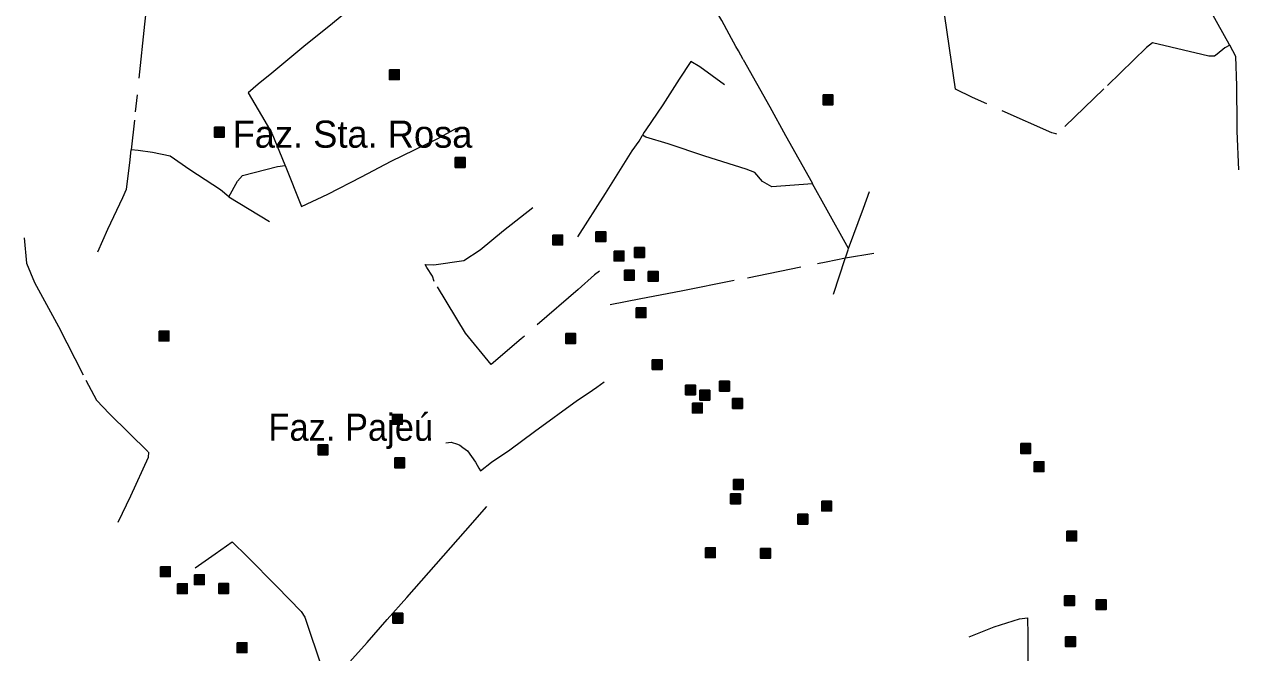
# Model space of a CAD drawing. Extents: x 393.5 to 446.9, y 8064.8 to 8120.4.
# Drawn here: x 410.47 to 417.64, y 8111.65 to 8115.35 of the extents above; entities that cross this region are included whole.
import ezdxf

# ---------------------------------------------------------------- set-up
doc = ezdxf.new("R2010")
doc.units = 0
doc.header["$LTSCALE"] = 0.064
doc.linetypes.add('DOT_DASHED', pattern=[7.7, 5, -1.2, 0.3, -1.2])
doc.layers.add('2', color=7, linetype='Continuous', lineweight=25)
doc.layers.add('22', color=7, linetype='DOT_DASHED', lineweight=13)
doc.layers.add('61', color=7, linetype='Continuous')

msp = doc.modelspace()

# ---------------------------------------------------------------- hatches: boundary and pattern name
at = {"layer": '2'}
for points in [[(412.626, 8115.0857), (412.684, 8115.0857), (412.684, 8115.0277), (412.626, 8115.0277)], [(415.185, 8114.9373), (415.243, 8114.9373), (415.243, 8114.8793), (415.185, 8114.8793)], [(411.5929, 8114.7465), (411.6509, 8114.7465), (411.6509, 8114.6885), (411.5929, 8114.6885)], [(413.0148, 8114.5678), (413.0728, 8114.5678), (413.0728, 8114.5098), (413.0148, 8114.5098)], [(413.5902, 8114.1105), (413.6482, 8114.1105), (413.6482, 8114.0525), (413.5902, 8114.0525)], [(413.8448, 8114.1301), (413.9028, 8114.1301), (413.9028, 8114.0721), (413.8448, 8114.0721)], [(413.9519, 8114.016), (414.0099, 8114.016), (414.0099, 8113.958), (413.9519, 8113.958)], [(414.0725, 8114.036), (414.1305, 8114.036), (414.1305, 8113.978), (414.0725, 8113.978)], [(414.0122, 8113.9022), (414.0702, 8113.9022), (414.0702, 8113.8442), (414.0122, 8113.8442)], [(414.1529, 8113.8953), (414.2109, 8113.8953), (414.2109, 8113.8373), (414.1529, 8113.8373)], [(414.0812, 8113.6809), (414.1392, 8113.6809), (414.1392, 8113.6229), (414.0812, 8113.6229)], [(411.2667, 8113.5433), (411.3247, 8113.5433), (411.3247, 8113.4853), (411.2667, 8113.4853)], [(413.6664, 8113.5291), (413.7244, 8113.5291), (413.7244, 8113.4711), (413.6664, 8113.4711)], [(414.177, 8113.3748), (414.235, 8113.3748), (414.235, 8113.3168), (414.177, 8113.3168)], [(414.3733, 8113.2253), (414.4313, 8113.2253), (414.4313, 8113.1673), (414.3733, 8113.1673)], [(414.5742, 8113.2475), (414.6322, 8113.2475), (414.6322, 8113.1895), (414.5742, 8113.1895)], [(414.4582, 8113.1939), (414.5162, 8113.1939), (414.5162, 8113.1359), (414.4582, 8113.1359)], [(414.6506, 8113.1449), (414.7086, 8113.1449), (414.7086, 8113.0869), (414.6506, 8113.0869)], [(414.414, 8113.1183), (414.472, 8113.1183), (414.472, 8113.0603), (414.414, 8113.0603)], [(412.6438, 8113.0521), (412.7018, 8113.0521), (412.7018, 8112.9941), (412.6438, 8112.9941)], [(412.2047, 8112.8714), (412.2627, 8112.8714), (412.2627, 8112.8134), (412.2047, 8112.8134)], [(416.3509, 8112.8795), (416.4089, 8112.8795), (416.4089, 8112.8215), (416.3509, 8112.8215)], [(412.6574, 8112.7951), (412.7154, 8112.7951), (412.7154, 8112.7371), (412.6574, 8112.7371)], [(416.43, 8112.7725), (416.488, 8112.7725), (416.488, 8112.7145), (416.43, 8112.7145)], [(414.6554, 8112.6666), (414.7134, 8112.6666), (414.7134, 8112.6086), (414.6554, 8112.6086)], [(414.6391, 8112.5823), (414.6971, 8112.5823), (414.6971, 8112.5243), (414.6391, 8112.5243)], [(415.1773, 8112.5397), (415.2353, 8112.5397), (415.2353, 8112.4817), (415.1773, 8112.4817)], [(415.0364, 8112.4625), (415.0944, 8112.4625), (415.0944, 8112.4045), (415.0364, 8112.4045)], [(416.6232, 8112.3635), (416.6812, 8112.3635), (416.6812, 8112.3055), (416.6232, 8112.3055)], [(414.4907, 8112.2645), (414.5487, 8112.2645), (414.5487, 8112.2065), (414.4907, 8112.2065)], [(414.8157, 8112.2609), (414.8737, 8112.2609), (414.8737, 8112.2029), (414.8157, 8112.2029)], [(411.2747, 8112.1528), (411.3327, 8112.1528), (411.3327, 8112.0948), (411.2747, 8112.0948)], [(411.4754, 8112.1058), (411.5334, 8112.1058), (411.5334, 8112.0478), (411.4754, 8112.0478)], [(411.3752, 8112.0521), (411.4332, 8112.0521), (411.4332, 8111.9941), (411.3752, 8111.9941)], [(411.6189, 8112.053), (411.6769, 8112.053), (411.6769, 8111.995), (411.6189, 8111.995)], [(416.6096, 8111.9813), (416.6676, 8111.9813), (416.6676, 8111.9233), (416.6096, 8111.9233)], [(416.797, 8111.9577), (416.855, 8111.9577), (416.855, 8111.8997), (416.797, 8111.8997)], [(412.647, 8111.878), (412.705, 8111.878), (412.705, 8111.82), (412.647, 8111.82)], [(416.6161, 8111.7398), (416.6741, 8111.7398), (416.6741, 8111.6818), (416.6161, 8111.6818)], [(411.7272, 8111.7039), (411.7852, 8111.7039), (411.7852, 8111.6459), (411.7272, 8111.6459)]]:
    msp.add_hatch(color=256, dxfattribs=at).paths.add_polyline_path(points)

# ---------------------------------------------------------------- linework, layer by layer
for points in [[(412.626, 8115.0857), (412.684, 8115.0857), (412.684, 8115.0277), (412.626, 8115.0277)], [(415.185, 8114.9373), (415.243, 8114.9373), (415.243, 8114.8793), (415.185, 8114.8793)], [(411.5929, 8114.7465), (411.6509, 8114.7465), (411.6509, 8114.6885), (411.5929, 8114.6885)], [(413.0148, 8114.5678), (413.0728, 8114.5678), (413.0728, 8114.5098), (413.0148, 8114.5098)], [(413.5902, 8114.1105), (413.6482, 8114.1105), (413.6482, 8114.0525), (413.5902, 8114.0525)], [(413.8448, 8114.1301), (413.9028, 8114.1301), (413.9028, 8114.0721), (413.8448, 8114.0721)], [(413.9519, 8114.016), (414.0099, 8114.016), (414.0099, 8113.958), (413.9519, 8113.958)], [(414.0725, 8114.036), (414.1305, 8114.036), (414.1305, 8113.978), (414.0725, 8113.978)], [(414.0122, 8113.9022), (414.0702, 8113.9022), (414.0702, 8113.8442), (414.0122, 8113.8442)], [(414.1529, 8113.8953), (414.2109, 8113.8953), (414.2109, 8113.8373), (414.1529, 8113.8373)], [(414.0812, 8113.6809), (414.1392, 8113.6809), (414.1392, 8113.6229), (414.0812, 8113.6229)], [(411.2667, 8113.5433), (411.3247, 8113.5433), (411.3247, 8113.4853), (411.2667, 8113.4853)], [(413.6664, 8113.5291), (413.7244, 8113.5291), (413.7244, 8113.4711), (413.6664, 8113.4711)], [(414.177, 8113.3748), (414.235, 8113.3748), (414.235, 8113.3168), (414.177, 8113.3168)], [(414.3733, 8113.2253), (414.4313, 8113.2253), (414.4313, 8113.1673), (414.3733, 8113.1673)], [(414.5742, 8113.2475), (414.6322, 8113.2475), (414.6322, 8113.1895), (414.5742, 8113.1895)], [(414.4582, 8113.1939), (414.5162, 8113.1939), (414.5162, 8113.1359), (414.4582, 8113.1359)], [(414.6506, 8113.1449), (414.7086, 8113.1449), (414.7086, 8113.0869), (414.6506, 8113.0869)], [(414.414, 8113.1183), (414.472, 8113.1183), (414.472, 8113.0603), (414.414, 8113.0603)], [(412.6438, 8113.0521), (412.7018, 8113.0521), (412.7018, 8112.9941), (412.6438, 8112.9941)], [(412.2047, 8112.8714), (412.2627, 8112.8714), (412.2627, 8112.8134), (412.2047, 8112.8134)], [(416.3509, 8112.8795), (416.4089, 8112.8795), (416.4089, 8112.8215), (416.3509, 8112.8215)], [(412.6574, 8112.7951), (412.7154, 8112.7951), (412.7154, 8112.7371), (412.6574, 8112.7371)], [(416.43, 8112.7725), (416.488, 8112.7725), (416.488, 8112.7145), (416.43, 8112.7145)], [(414.6554, 8112.6666), (414.7134, 8112.6666), (414.7134, 8112.6086), (414.6554, 8112.6086)], [(414.6391, 8112.5823), (414.6971, 8112.5823), (414.6971, 8112.5243), (414.6391, 8112.5243)], [(415.1773, 8112.5397), (415.2353, 8112.5397), (415.2353, 8112.4817), (415.1773, 8112.4817)], [(415.0364, 8112.4625), (415.0944, 8112.4625), (415.0944, 8112.4045), (415.0364, 8112.4045)], [(416.6232, 8112.3635), (416.6812, 8112.3635), (416.6812, 8112.3055), (416.6232, 8112.3055)], [(414.4907, 8112.2645), (414.5487, 8112.2645), (414.5487, 8112.2065), (414.4907, 8112.2065)], [(414.8157, 8112.2609), (414.8737, 8112.2609), (414.8737, 8112.2029), (414.8157, 8112.2029)], [(411.2747, 8112.1528), (411.3327, 8112.1528), (411.3327, 8112.0948), (411.2747, 8112.0948)], [(411.4754, 8112.1058), (411.5334, 8112.1058), (411.5334, 8112.0478), (411.4754, 8112.0478)], [(411.3752, 8112.0521), (411.4332, 8112.0521), (411.4332, 8111.9941), (411.3752, 8111.9941)], [(411.6189, 8112.053), (411.6769, 8112.053), (411.6769, 8111.995), (411.6189, 8111.995)], [(416.6096, 8111.9813), (416.6676, 8111.9813), (416.6676, 8111.9233), (416.6096, 8111.9233)], [(416.797, 8111.9577), (416.855, 8111.9577), (416.855, 8111.8997), (416.797, 8111.8997)], [(412.647, 8111.878), (412.705, 8111.878), (412.705, 8111.82), (412.647, 8111.82)], [(416.6161, 8111.7398), (416.6741, 8111.7398), (416.6741, 8111.6818), (416.6161, 8111.6818)], [(411.7272, 8111.7039), (411.7852, 8111.7039), (411.7852, 8111.6459), (411.7272, 8111.6459)]]:
    msp.add_lwpolyline(points, close=True, dxfattribs=at)
at = {"layer": '22'}
msp.add_line((411.6777, 8114.335), (411.9173, 8114.1896), dxfattribs=at)
for points in [[(411.2761, 8116.2577), (411.2398, 8115.888), (411.1999, 8115.535), (411.181, 8115.3547), (411.1208, 8114.7887), (411.1018, 8114.6125)], [(417.4196, 8115.1753), (417.1289, 8115.2452), (417.0932, 8115.2163), (416.8425, 8114.9734), (416.5646, 8114.705), (416.5578, 8114.7067), (416.534, 8114.7135), (416.0674, 8114.9224), (415.9672, 8114.9717), (415.9307, 8115.213), (415.8879, 8115.5118), (415.8432, 8115.8113)], [(412.7316, 8115.7173), (412.6162, 8115.6321), (412.4375, 8115.4816), (412.2905, 8115.358), (412.1208, 8115.223), (411.9325, 8115.0664), (411.8511, 8115.001), (411.7923, 8114.9492), (411.8715, 8114.8157), (411.9327, 8114.7117), (412.009, 8114.5255), (412.0108, 8114.5212)], [(414.6705, 8115.2225), (414.6316, 8115.2957), (414.5865, 8115.3768), (414.5269, 8115.4781), (414.5028, 8115.5224)], [(417.5809, 8115.2364), (417.4797, 8115.4193), (417.4368, 8115.5034), (417.4365, 8115.504)], [(415.1216, 8114.4167), (414.9658, 8114.6961), (414.872, 8114.8646), (414.7142, 8115.1461), (414.6851, 8115.1984), (414.6705, 8115.2225)], [(417.5844, 8115.2301), (417.5548, 8115.2143), (417.5106, 8115.177), (417.4953, 8115.1668), (417.4817, 8115.1668), (417.4613, 8115.1668), (417.4196, 8115.1753)], [(417.5844, 8115.2301), (417.5835, 8115.2317), (417.5809, 8115.2364)], [(417.6271, 8114.9914), (417.621, 8115.1637), (417.5844, 8115.2301)], [(414.6037, 8114.9965), (414.4583, 8115.104), (414.4045, 8115.1345), (414.3347, 8115.0299), (414.2402, 8114.8788), (414.1399, 8114.7306), (414.1298, 8114.7165), (414.1196, 8114.6991)], [(417.6289, 8114.825), (417.6262, 8114.9269), (417.6271, 8114.9914)], [(417.6375, 8114.4945), (417.6279, 8114.7231), (417.6289, 8114.825)], [(412.0108, 8114.5212), (412.1066, 8114.2797), (412.2622, 8114.3518), (412.4606, 8114.4532), (412.6364, 8114.5455), (412.9115, 8114.6807), (413.022, 8114.7415)], [(413.7368, 8114.1004), (413.9008, 8114.3554), (414.0588, 8114.6082), (414.0996, 8114.6634), (414.1181, 8114.6964), (414.1182, 8114.6965), (414.1196, 8114.6991)], [(415.1234, 8114.4135), (414.8819, 8114.3943), (414.8277, 8114.4272), (414.7812, 8114.4795), (414.7308, 8114.4989), (414.4867, 8114.5763), (414.2717, 8114.6479), (414.1385, 8114.6889), (414.1196, 8114.6991)], [(410.9061, 8114.0113), (410.9646, 8114.1444), (411.0533, 8114.3313), (411.0745, 8114.3814), (411.0938, 8114.5374), (411.1018, 8114.6125)], [(411.6777, 8114.335), (411.6298, 8114.3769), (411.4486, 8114.4944), (411.3329, 8114.5753), (411.2269, 8114.5984), (411.144, 8114.61), (411.1018, 8114.6125)], [(411.6777, 8114.335), (411.7301, 8114.4284), (411.7595, 8114.4622), (411.9646, 8114.514), (412.0108, 8114.5212)], [(415.3358, 8114.0311), (415.1992, 8114.2743), (415.1234, 8114.4135), (415.1216, 8114.4167)], [(415.3358, 8114.0311), (415.4225, 8114.2693), (415.458, 8114.3678)], [(412.8474, 8113.919), (412.8378, 8113.9373), (412.8878, 8113.9336), (413.0658, 8113.9595), (413.1622, 8114.0233), (413.2992, 8114.1365), (413.4717, 8114.2735)], [(410.4713, 8114.0941), (410.4837, 8113.9436), (410.5325, 8113.8297), (410.6736, 8113.5701), (410.8346, 8113.2534), (410.8971, 8113.1363), (410.9739, 8113.0549), (411.2043, 8112.8294), (411.202, 8112.7968), (411.0972, 8112.569), (411.0228, 8112.4132)], [(415.246, 8113.7616), (415.3158, 8113.9715), (415.3175, 8113.9766), (415.485, 8114.0043)], [(415.3175, 8113.9766), (415.3331, 8114.0236), (415.3358, 8114.0311)], [(413.9289, 8113.701), (414.1101, 8113.7367), (414.3472, 8113.7813), (414.7394, 8113.8587), (415.2032, 8113.9527), (415.3175, 8113.9766)], [(413.865, 8113.8978), (413.8369, 8113.8764), (413.7405, 8113.7894), (413.4042, 8113.4978), (413.2262, 8113.3467), (413.0744, 8113.5303), (412.89, 8113.8363), (412.8797, 8113.8671), (412.8474, 8113.919)], [(413.7991, 8113.178), (413.8491, 8113.2116), (413.8932, 8113.2432)], [(412.9596, 8112.8838), (412.9911, 8112.8877), (413.0281, 8112.8759), (413.042, 8112.8697), (413.0592, 8112.8573), (413.0857, 8112.8371), (413.134, 8112.7703), (413.1542, 8112.7346), (413.1636, 8112.719), (413.2289, 8112.7702), (413.3364, 8112.8432), (413.4812, 8112.9502), (413.7349, 8113.1355), (413.7991, 8113.178)], [(411.4804, 8112.1456), (411.5982, 8112.2282), (411.6975, 8112.3005), (411.7874, 8112.2138), (411.9611, 8112.0361), (412.1058, 8111.8894), (412.1275, 8111.8543), (412.2329, 8111.5382), (412.2639, 8111.4535), (412.3224, 8111.5122), (412.4955, 8111.7052), (412.6124, 8111.841), (412.7289, 8111.9706), (412.9009, 8112.1678), (413.074, 8112.3638), (413.2005, 8112.5088)], [(416.0478, 8111.7387), (416.1944, 8111.7984), (416.3436, 8111.8457), (416.3908, 8111.8507), (416.3932, 8111.7491), (416.393, 8111.5357), (416.3013, 8111.5031), (416.244, 8111.4806)]]:
    msp.add_lwpolyline(points, dxfattribs=at)

# ---------------------------------------------------------------- texts
at = {"layer": '61'}
msp.add_text('Faz. Sta. Rosa', height=0.16, dxfattribs=at).set_placement((411.7005, 8114.6258))
at = {"layer": '61', "width": 0.95}
msp.add_text('Faz. Pajeú', height=0.16, dxfattribs=at).set_placement((411.9121, 8112.8961))

doc.saveas('drawing.dxf')
